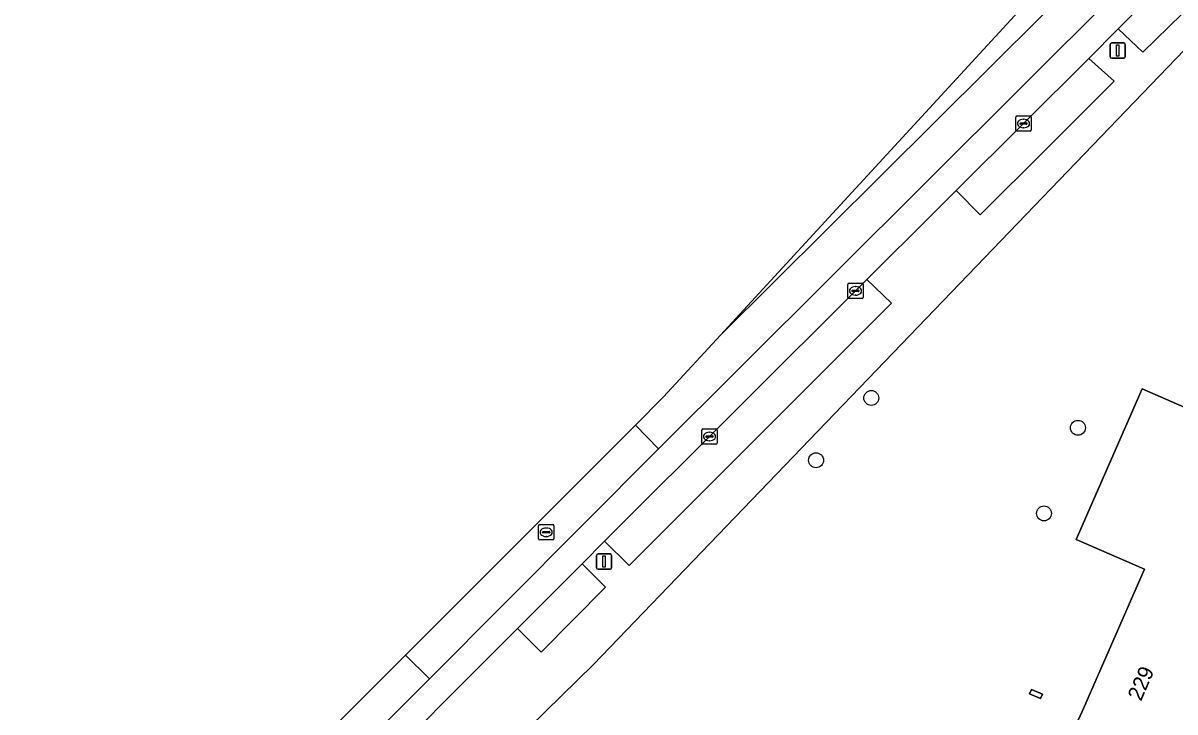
# Model space of a CAD drawing. Extents: x 160349 to 161355, y 381727 to 382854.
# Drawn here: x 160405.1 to 160480.7, y 382144 to 382189.2 of the extents above; entities that cross this region are included whole.
import ezdxf

# ---------------------------------------------------------------- set-up
doc = ezdxf.new("R2010")
doc.units = 0
for name, color, linetype in [('IMGEO_Boom', 7, 'Continuous'), ('IMGEO_Erf', 7, 'Continuous'), ('IMGEO_Kolk', 7, 'Continuous'), ('IMGEO_Lichtmast', 7, 'Continuous'), ('IMGEO_Pand', 7, 'Continuous'), ('IMGEO_Pand_nummerreeks', 7, 'Continuous'), ('IMGEO_Parkeervlak_open', 7, 'Continuous'), ('IMGEO_Rijbaan_lokaal_gesloten', 7, 'Continuous'), ('IMGEO_Rijbaan_lokaal_open', 7, 'Continuous'), ('IMGEO_Rioolput', 7, 'Continuous'), ('IMGEO_Voetpad_open', 7, 'Continuous')]:
    doc.layers.add(name, color=color, linetype=linetype)

msp = doc.modelspace()

# ---------------------------------------------------------------- linework, layer by layer
at = {"layer": 'IMGEO_Boom'}
for centre in [(160460.746, 382164.603), (160474.313, 382162.641), (160457.121, 382160.513), (160472.085, 382157.021)]:
    msp.add_circle(centre, 0.489, dxfattribs=at)
at = {"layer": 'IMGEO_Erf'}
for points in [[(160481.828, 382188.002), (160442.501, 382147.099), (160436.177, 382140.906), (160414.747, 382119.51), (160411.966, 382116.562), (160403.61, 382106.983), (160399.063, 382101.977), (160394.41, 382096.662), (160404.73, 382089.236), (160405.11, 382089.807), (160407.736, 382093.752), (160417.915, 382086.892), (160417.702, 382086.577), (160447.683, 382064.351), (160432.148, 382043.338)], [(160473.257, 382141.119), (160474.597, 382144.015), (160478.68, 382153.35), (160474.2, 382155.306), (160478.523, 382165.202), (160494.77, 382158.105)]]:
    msp.add_lwpolyline(points, dxfattribs=at)
msp.add_lwpolyline([(160471.145, 382145.176), (160471.274, 382145.469), (160471.979, 382145.161), (160471.851, 382144.867)], close=True, dxfattribs=at)
at = {"layer": 'IMGEO_Kolk'}
for p, q in [((160470.242, 382182.195), (160470.242, 382183.047)), ((160470.317, 382183.121), (160471.169, 382183.121)), ((160471.243, 382183.047), (160471.243, 382182.195)), ((160470.501, 382182.615), (160470.501, 382182.627)), ((160470.939, 382182.578), (160470.541, 382182.578)), ((160470.544, 382182.664), (160470.942, 382182.664)), ((160470.753, 382182.341), (160470.728, 382182.341)), ((160470.73, 382182.901), (160470.755, 382182.901)), ((160470.985, 382182.627), (160470.985, 382182.615)), ((160471.169, 382182.121), (160470.317, 382182.121)), ((160459.21, 382171.207), (160459.21, 382172.059)), ((160459.285, 382172.133), (160460.137, 382172.133)), ((160459.512, 382171.676), (160459.91, 382171.676)), ((160459.698, 382171.913), (160459.723, 382171.913)), ((160460.211, 382172.059), (160460.211, 382171.207)), ((160460.137, 382171.133), (160459.285, 382171.133)), ((160459.469, 382171.627), (160459.469, 382171.639)), ((160459.907, 382171.59), (160459.509, 382171.59)), ((160459.721, 382171.353), (160459.696, 382171.353)), ((160459.953, 382171.639), (160459.953, 382171.627)), ((160449.621, 382161.644), (160449.621, 382162.496)), ((160449.696, 382162.57), (160450.548, 382162.57)), ((160449.88, 382162.064), (160449.88, 382162.076)), ((160450.318, 382162.027), (160449.92, 382162.027)), ((160449.923, 382162.113), (160450.321, 382162.113)), ((160450.109, 382162.35), (160450.134, 382162.35)), ((160450.364, 382162.076), (160450.364, 382162.064)), ((160450.622, 382162.496), (160450.622, 382161.644)), ((160450.548, 382161.57), (160449.696, 382161.57)), ((160450.132, 382161.79), (160450.107, 382161.79))]:
    msp.add_line(p, q, dxfattribs=at)
for points in [[(160470.242, 382182.195), (160470.242, 382183.047)], [(160470.317, 382183.121), (160471.169, 382183.121)], [(160471.243, 382183.047), (160471.243, 382182.195)], [(160471.169, 382182.121), (160470.317, 382182.121)], [(160459.21, 382171.207), (160459.21, 382172.059)], [(160459.285, 382172.133), (160460.137, 382172.133)], [(160460.211, 382172.059), (160460.211, 382171.207)], [(160460.137, 382171.133), (160459.285, 382171.133)], [(160449.621, 382161.644), (160449.621, 382162.496)], [(160449.696, 382162.57), (160450.548, 382162.57)], [(160450.622, 382162.496), (160450.622, 382161.644)], [(160450.548, 382161.57), (160449.696, 382161.57)]]:
    msp.add_lwpolyline(points, dxfattribs=at)
for centre, radius, start, end in [((160470.319, 382183.045), 0.0765, 91.55205, 178.44795), ((160470.319, 382183.045), 0.0765, 91.55205, 178.44795), ((160471.167, 382183.045), 0.0765, 1.55205, 88.44795), ((160471.167, 382183.045), 0.0765, 1.55205, 88.44795), ((160470.541, 382182.624), 0.0403, 85.87752, 175.75265), ((160470.538, 382182.614), 0.0366, 178.93798, 274.71019), ((160470.942, 382182.621), 0.043, 264.86636, 352.45326), ((160470.946, 382182.626), 0.0386, 1.73085, 96.63898), ((160470.319, 382182.197), 0.0765, 181.55205, 268.44795), ((160470.319, 382182.197), 0.0765, 181.55205, 268.44795), ((160471.167, 382182.197), 0.0765, 271.55205, 358.44795), ((160471.167, 382182.197), 0.0765, 271.55205, 358.44795), ((160459.287, 382172.057), 0.0765, 91.55205, 178.44795), ((160459.287, 382172.057), 0.0765, 91.55205, 178.44795), ((160459.509, 382171.636), 0.0403, 85.87752, 175.75265), ((160459.914, 382171.638), 0.0386, 1.73085, 96.63898), ((160460.135, 382172.057), 0.0765, 1.55205, 88.44795), ((160460.135, 382172.057), 0.0765, 1.55205, 88.44795), ((160459.287, 382171.209), 0.0765, 181.55205, 268.44795), ((160459.287, 382171.209), 0.0765, 181.55205, 268.44795), ((160459.506, 382171.626), 0.0366, 178.93798, 274.71019), ((160459.91, 382171.633), 0.043, 264.86636, 352.45326), ((160460.135, 382171.209), 0.0765, 271.55205, 358.44795), ((160460.135, 382171.209), 0.0765, 271.55205, 358.44795), ((160449.698, 382162.494), 0.0765, 91.55205, 178.44795), ((160449.698, 382162.494), 0.0765, 91.55205, 178.44795), ((160449.92, 382162.073), 0.0403, 85.87752, 175.75265), ((160449.917, 382162.063), 0.0366, 178.93798, 274.71019), ((160450.321, 382162.07), 0.043, 264.86636, 352.45326), ((160450.325, 382162.075), 0.0386, 1.73085, 96.63898), ((160450.546, 382162.494), 0.0765, 1.55205, 88.44795), ((160450.546, 382162.494), 0.0765, 1.55205, 88.44795), ((160449.698, 382161.646), 0.0765, 181.55205, 268.44795), ((160449.698, 382161.646), 0.0765, 181.55205, 268.44795), ((160450.546, 382161.646), 0.0765, 271.55205, 358.44795), ((160450.546, 382161.646), 0.0765, 271.55205, 358.44795)]:
    msp.add_arc(centre, radius, start, end, dxfattribs=at)
for centre, major_axis, ratio, start_param, end_param in [((160470.729, 382182.621), (-0.387, 0.002), 0.722429, 4.712389, 7.853982), ((160470.754, 382182.621), (-0.39, 0.002), 0.717154, 1.570796, 4.712389), ((160459.697, 382171.633), (-0.387, 0.002), 0.722429, 4.712389, 7.853982), ((160459.722, 382171.633), (-0.39, 0.002), 0.717154, 1.570796, 4.712389), ((160450.108, 382162.07), (-0.387, 0.002), 0.722429, 4.712389, 7.853982), ((160450.133, 382162.07), (-0.39, 0.002), 0.717154, 1.570796, 4.712389)]:
    msp.add_ellipse(centre, major_axis=major_axis, ratio=ratio, start_param=start_param, end_param=end_param, dxfattribs=at)
at = {"layer": 'IMGEO_Lichtmast'}
for p, q in [((160476.431, 382187.011), (160476.431, 382187.811)), ((160476.431, 382187.811), (160476.431, 382187.011)), ((160476.531, 382187.911), (160477.321, 382187.911)), ((160477.321, 382187.911), (160476.531, 382187.911)), ((160477.421, 382187.811), (160477.421, 382187.011)), ((160477.421, 382187.011), (160477.421, 382187.811)), ((160477.321, 382186.911), (160476.531, 382186.911)), ((160476.531, 382186.911), (160477.321, 382186.911)), ((160442.804, 382154.357), (160443.594, 382154.357)), ((160443.594, 382154.357), (160442.804, 382154.357)), ((160442.704, 382153.457), (160442.704, 382154.257)), ((160442.704, 382154.257), (160442.704, 382153.457)), ((160443.694, 382154.257), (160443.694, 382153.457)), ((160443.694, 382153.457), (160443.694, 382154.257)), ((160443.594, 382153.357), (160442.804, 382153.357)), ((160442.804, 382153.357), (160443.594, 382153.357))]:
    msp.add_line(p, q, dxfattribs=at)
for points in [[(160476.851, 382187.786), (160477.001, 382187.786), (160477.001, 382187.036), (160476.851, 382187.036), (160476.851, 382187.786)], [(160443.124, 382154.232), (160443.274, 382154.232), (160443.274, 382153.482), (160443.124, 382153.482), (160443.124, 382154.232)]]:
    msp.add_lwpolyline(points, dxfattribs=at)
for centre, start, end in [((160476.531, 382187.811), 90, 180), ((160476.531, 382187.811), 90, 180), ((160477.321, 382187.811), 0, 90), ((160477.321, 382187.811), 360, 90), ((160476.531, 382187.011), 180, 270), ((160476.531, 382187.011), 180, 270), ((160477.321, 382187.011), 270, 0), ((160477.321, 382187.011), 270, 0), ((160442.804, 382154.257), 90, 180), ((160442.804, 382154.257), 90, 180), ((160443.594, 382154.257), 0, 90), ((160443.594, 382154.257), 360, 90), ((160442.804, 382153.457), 180, 270), ((160442.804, 382153.457), 180, 270), ((160443.594, 382153.457), 270, 0), ((160443.594, 382153.457), 270, 0)]:
    msp.add_arc(centre, 0.1, start, end, dxfattribs=at)
at = {"layer": 'IMGEO_Pand'}
msp.add_lwpolyline([(160494.77, 382158.105), (160478.523, 382165.202), (160474.2, 382155.306), (160478.68, 382153.35), (160474.597, 382144.015), (160473.257, 382141.119), (160473.163, 382140.909), (160476.519, 382139.409), (160475.974, 382138.19), (160478.129, 382137.227), (160473.306, 382126.435), (160473.746, 382126.238), (160471.998, 382122.328), (160476.32, 382120.38), (160476.21, 382120.12), (160477.825, 382119.406), (160479.101, 382122.324), (160485.098, 382119.701)], dxfattribs=at)
msp.add_lwpolyline([(160471.274, 382145.469), (160471.145, 382145.176), (160471.851, 382144.867), (160471.979, 382145.161)], close=True, dxfattribs=at)
at = {"layer": 'IMGEO_Parkeervlak_open'}
msp.add_lwpolyline([(160486.666, 382198.557), (160476.963, 382188.83), (160478.584, 382187.303), (160483.694, 382192.318), (160488.98, 382197.683), (160492.685, 382201.786), (160495.22, 382204.761), (160493.513, 382206.216)], dxfattribs=at)
for points in [[(160476.695, 382185.41), (160475.026, 382186.897), (160470.743, 382182.621), (160466.313, 382178.214), (160467.899, 382176.619), (160472.239, 382180.947)], [(160462.07, 382170.835), (160460.462, 382172.382), (160443.24, 382155.193), (160444.846, 382153.61)], [(160443.291, 382152.188), (160441.753, 382153.708), (160437.507, 382149.466), (160439.064, 382147.901)]]:
    msp.add_lwpolyline(points, close=True, dxfattribs=at)
at = {"layer": 'IMGEO_Rijbaan_lokaal_gesloten'}
for points in [[(160450.854, 382168.735), (160461.421, 382179.236), (160479.16, 382196.897), (160485.768, 382203.713), (160488.191, 382206.418), (160518.337, 382242.093), (160490.012, 382211.302), (160486.762, 382207.445), (160482.017, 382202.324), (160481.716, 382202.019), (160478.755, 382199.065), (160475.495, 382195.521), (160450.854, 382168.735)], [(160464.853, 382176.761), (160466.313, 382178.214), (160470.743, 382182.621), (160475.026, 382186.897), (160476.963, 382188.83), (160486.666, 382198.557)], [(160482.965, 382197.347), (160452.104, 382166.578), (160446.775, 382161.263), (160431.731, 382146.162), (160425.683, 382140.065), (160396.112, 382109.878), (160394.197, 382107.923)], [(160397.007, 382108.218), (160413.982, 382125.549), (160422.374, 382134.126), (160423.857, 382135.644), (160428.067, 382139.946), (160432.845, 382144.808), (160437.507, 382149.466), (160441.753, 382153.708), (160443.24, 382155.193), (160460.462, 382172.382), (160464.853, 382176.761)]]:
    msp.add_lwpolyline(points, dxfattribs=at)
at = {"layer": 'IMGEO_Rijbaan_lokaal_open'}
for points in [[(160491.199, 382206.25), (160544.163, 382268.947), (160548.551, 382274.127), (160549.933, 382272.986), (160550.319, 382273.443), (160546.848, 382276.289), (160546.482, 382275.816), (160546.674, 382275.658), (160542.854, 382271.114), (160536.882, 382263.373), (160531.527, 382256.432), (160518.337, 382242.093), (160488.191, 382206.418), (160485.768, 382203.713), (160479.16, 382196.897), (160461.421, 382179.236), (160450.854, 382168.735), (160447.11, 382164.665), (160445.256, 382162.81)], [(160445.256, 382162.81), (160446.775, 382161.263), (160452.104, 382166.578), (160482.965, 382197.347)]]:
    msp.add_lwpolyline(points, dxfattribs=at)
for points in [[(160430.168, 382147.718), (160431.731, 382146.162), (160446.775, 382161.263), (160445.256, 382162.81)], [(160394.184, 382111.721), (160396.112, 382109.878), (160425.683, 382140.065), (160431.731, 382146.162), (160430.168, 382147.718)]]:
    msp.add_lwpolyline(points, close=True, dxfattribs=at)
at = {"layer": 'IMGEO_Rioolput'}
for p, q in [((160438.899, 382155.357), (160438.899, 382156.209)), ((160438.974, 382156.283), (160439.826, 382156.283)), ((160439.158, 382155.777), (160439.158, 382155.789)), ((160439.201, 382155.826), (160439.599, 382155.826)), ((160439.387, 382156.063), (160439.412, 382156.063)), ((160439.642, 382155.789), (160439.642, 382155.777)), ((160439.9, 382156.209), (160439.9, 382155.357)), ((160439.826, 382155.283), (160438.974, 382155.283)), ((160439.596, 382155.74), (160439.198, 382155.74)), ((160439.41, 382155.503), (160439.385, 382155.503))]:
    msp.add_line(p, q, dxfattribs=at)
for points in [[(160438.899, 382155.357), (160438.899, 382156.209)], [(160438.974, 382156.283), (160439.826, 382156.283)], [(160439.9, 382156.209), (160439.9, 382155.357)], [(160439.826, 382155.283), (160438.974, 382155.283)]]:
    msp.add_lwpolyline(points, dxfattribs=at)
for centre, radius, start, end in [((160438.976, 382156.207), 0.0765, 91.55205, 178.44795), ((160438.976, 382156.207), 0.0765, 91.55205, 178.44795), ((160439.198, 382155.786), 0.0403, 85.87752, 175.75265), ((160439.603, 382155.788), 0.0386, 1.73085, 96.63898), ((160439.824, 382156.207), 0.0765, 1.55205, 88.44795), ((160439.824, 382156.207), 0.0765, 1.55205, 88.44795), ((160438.976, 382155.359), 0.0765, 181.55205, 268.44795), ((160438.976, 382155.359), 0.0765, 181.55205, 268.44795), ((160439.195, 382155.776), 0.0366, 178.93798, 274.71019), ((160439.599, 382155.783), 0.043, 264.86636, 352.45326), ((160439.824, 382155.359), 0.0765, 271.55205, 358.44795), ((160439.824, 382155.359), 0.0765, 271.55205, 358.44795)]:
    msp.add_arc(centre, radius, start, end, dxfattribs=at)
for centre, major_axis, ratio, start_param, end_param in [((160439.386, 382155.783), (-0.387, 0.002), 0.722429, 4.712389, 7.853982), ((160439.411, 382155.783), (-0.39, 0.002), 0.717154, 1.570796, 4.712389)]:
    msp.add_ellipse(centre, major_axis=major_axis, ratio=ratio, start_param=start_param, end_param=end_param, dxfattribs=at)
at = {"layer": 'IMGEO_Voetpad_open'}
for points in [[(160483.694, 382192.318), (160478.584, 382187.303), (160476.963, 382188.83), (160475.026, 382186.897), (160476.695, 382185.41), (160472.239, 382180.947), (160467.899, 382176.619), (160466.313, 382178.214), (160464.853, 382176.761), (160460.462, 382172.382), (160462.07, 382170.835), (160444.846, 382153.61), (160443.24, 382155.193), (160441.753, 382153.708), (160443.291, 382152.188), (160439.064, 382147.901), (160437.507, 382149.466), (160432.845, 382144.808), (160428.067, 382139.946)], [(160381.127, 382058.365), (160386.161, 382062.607), (160385.211, 382064.753), (160383.638, 382066.55), (160383.352, 382068.809), (160382.372, 382070.877), (160382.897, 382073.161), (160382.568, 382075.516), (160383.693, 382077.527), (160384.068, 382079.878), (160385.674, 382081.443), (160387.034, 382083.29), (160385.405, 382084.474), (160394.41, 382096.662), (160399.063, 382101.977), (160403.61, 382106.983), (160411.966, 382116.562), (160414.747, 382119.51), (160436.177, 382140.906), (160442.501, 382147.099), (160481.828, 382188.002)]]:
    msp.add_lwpolyline(points, dxfattribs=at)

# ---------------------------------------------------------------- texts
at = {"layer": 'IMGEO_Pand_nummerreeks'}
msp.add_text('229', height=1, rotation=66.37716, dxfattribs=at).set_placement((160478.452, 382144.644))

doc.saveas('drawing.dxf')
